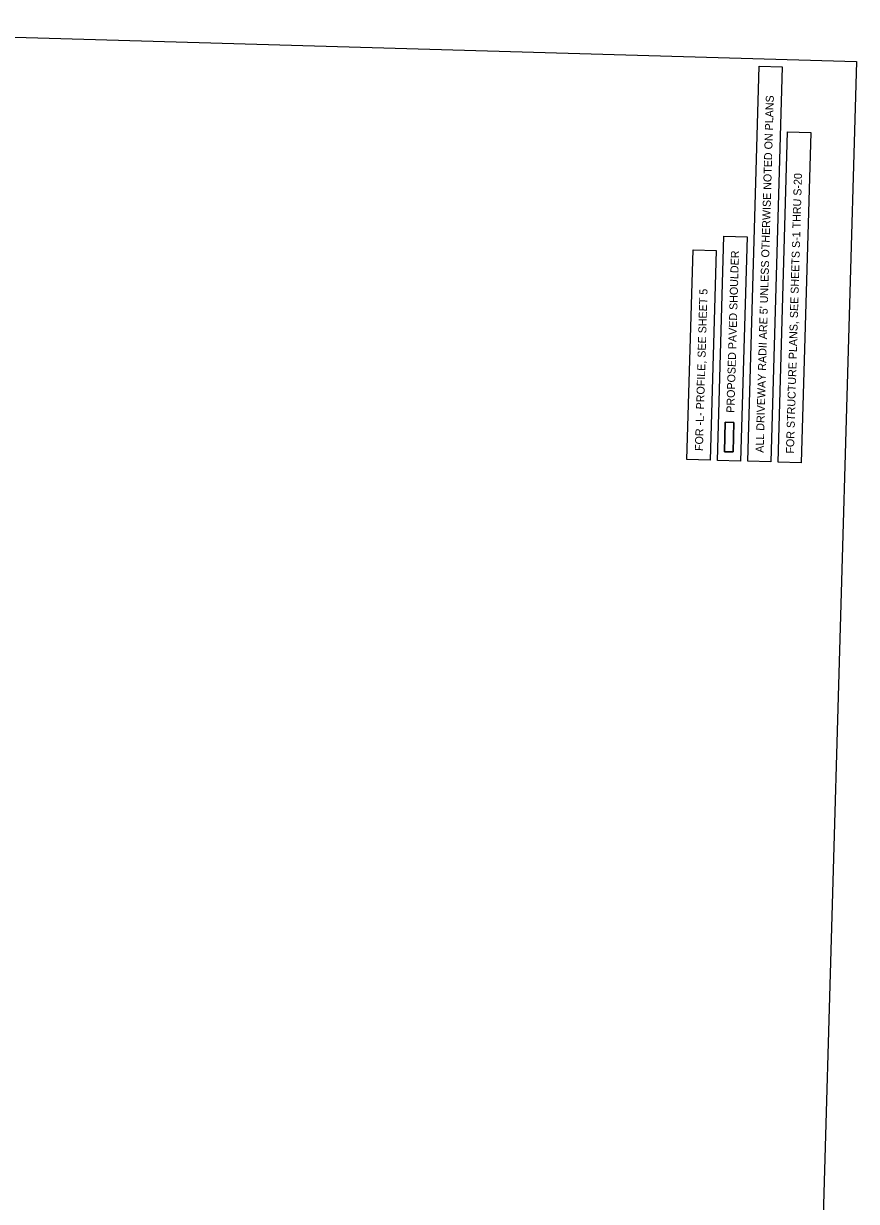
# Model space of a CAD drawing. Extents: x 2098230 to 2099272, y 990384 to 991889.
# Drawn here: x 2098751 to 2099272, y 991137 to 991873 of the extents above; entities that cross this region are included whole.
import ezdxf

# ---------------------------------------------------------------- set-up
doc = ezdxf.new("R2010")
doc.units = 0
for name, color, linetype in [('Prop Horizontal Alignment Station Label', 7, 'Continuous'), ('Prop Paved Shoulder', 7, 'Continuous'), ('Prop Shade Medium', 7, 'Continuous'), ('Sheet Layout Plan Border', 7, 'Continuous')]:
    doc.layers.add(name, color=color, linetype=linetype)

msp = doc.modelspace()

# ---------------------------------------------------------------- linework, layer by layer
at = {"layer": 'Prop Horizontal Alignment Station Label'}
for points in [[(2099225.24, 991845.82), (2099218.12, 991598.93), (2099203.59, 991599.34), (2099210.7, 991846.24)], [(2099243.05, 991804.93), (2099237.1, 991598.38), (2099222.56, 991598.8), (2099228.52, 991805.35)], [(2099203.19, 991739.65), (2099199.15, 991599.47), (2099184.61, 991599.89), (2099188.65, 991740.07)], [(2099183.95, 991731.14), (2099180.17, 991600.02), (2099165.64, 991600.44), (2099169.41, 991731.56)]]:
    msp.add_lwpolyline(points, close=True, dxfattribs=at)
at = {"layer": 'Prop Paved Shoulder'}
msp.add_lwpolyline([(2099189.04, 991605.34), (2099189.57, 991623.72), (2099194.96, 991623.56), (2099194.43, 991605.19)], close=True, dxfattribs=at)
at = {"layer": 'Prop Shade Medium'}
msp.add_lwpolyline([(2099194.43, 991605.19), (2099194.96, 991623.56), (2099189.57, 991623.72), (2099189.04, 991605.34)], close=True, dxfattribs=at)
at = {"layer": 'Sheet Layout Plan Border'}
msp.add_lwpolyline([(2098945.38, 990955.95), (2098929.61, 990408.49), (2098230.23, 990428.64), (2098266.23, 991678.07), (2098443.7, 991672.95), (2098449.47, 991872.92), (2099271.57, 991849.23), (2099245.59, 990947.3)], close=True, dxfattribs=at)
msp.add_lwpolyline([(2098945.38, 990955.95), (2098929.61, 990408.49), (2098230.23, 990428.64), (2098266.23, 991678.07), (2098443.7, 991672.95), (2098449.47, 991872.92), (2099271.57, 991849.23), (2099245.59, 990947.3)], close=True, dxfattribs=at)

# ---------------------------------------------------------------- texts
at = {"layer": 'Prop Horizontal Alignment Station Label'}
for s, p in [("ALL DRIVEWAY RADII ARE 5' UNLESS OTHERWISE NOTED ON PLANS", (2099213.52, 991604.64)), ('FOR STRUCTURE PLANS, SEE SHEETS S-1 THRU S-20', (2099232.49, 991604.09)), ('PROPOSED PAVED SHOULDER', (2099195.24, 991629.62)), ('FOR -L- PROFILE, SEE SHEET 5', (2099175.56, 991605.73))]:
    msp.add_text(s, height=5, rotation=88.34956, dxfattribs=at).set_placement(p)

doc.saveas('drawing.dxf')
